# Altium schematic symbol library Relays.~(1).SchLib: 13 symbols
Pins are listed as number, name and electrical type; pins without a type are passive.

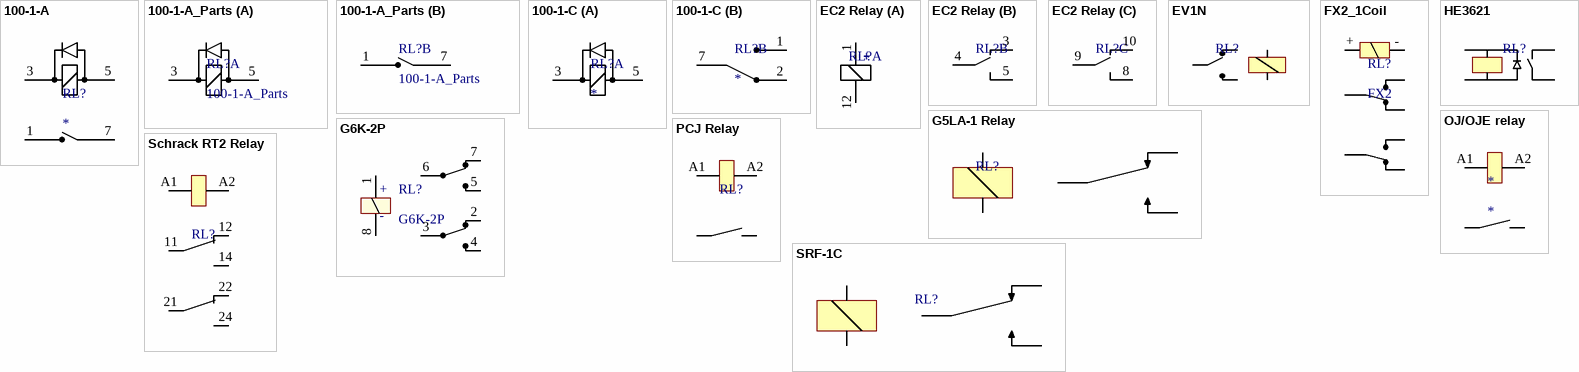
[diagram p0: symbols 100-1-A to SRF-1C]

## 100-1-A
designator RL?
footprint 100-1-A (Pickering Relay reed relay)
pins: 1 NO, 3 Coil+, 5 Coil-, 7 C

## 100-1-A_Parts
designator RL?
footprint 100-1-A (Pickering Relay reed relay)
part A pins: 3 Coil+, 5 Coil-
part B pins: 1 NO, 7 C

## 100-1-C
designator RL?
footprint 100-1-C (Pickering Relay reed relay)
part A pins: 3 Coil+, 5 Coil-
part B pins: 1 NO, 2 NC, 7 C

## EC2 Relay
designator RL?  (value not drawn)
footprint EC2 (EC2 series relay)
part A pins: 1 +, 12 -
part B pins: 3 NC, 4 C, 5 NO
part C pins: 8 NO, 9 C, 10 NC

## EV1N
designator RL?  (value not drawn)
footprint EV1N (Sub min relay)
pins: 1 NO, 2 Coil1, 3 Common, 5 Coil2, 6 NC

## FX2_1Coil
designator RL?, comment FX2
footprint FX2 relay 1 coil (FX2 relay with 1 coil); pin to pad +>1 ->10 C1>4 C2>7 NC1>3 NC2>8 NO1>5 NO2>6
pins: + COIL+, - COIL-, C1, C2, NC1, NC2, NO1, NO2

## G5LA-1 Relay
designator RL?  (value not drawn)
footprint G5LA-1 (10A CO relay)
pins: 1 Common, 2 Coil1, 3 NO, 4 NC, 5 Coil2

## G6K-2P
designator RL?
footprint G6K-2P (G6K-2P relay)
pins: 1 +, 2 NC2, 3 C2, 4 NO2, 5 NO1, 6 C1, 7 NC1, 8 -

## HE3621
designator RL?  (value not drawn)
footprint HE3621 (Hamlin Reed Relay)
pins: 1 NO, 2 +, 3 -, 4 C

## OJ/OJE relay
designator *
footprint Tyco OJ Relay (Tyco OJ/OJE relay High isolation contact/coil); pin to pad A1>1 A2>4 C>2 NO>3
pins: A1, A2, C, NO

## PCJ Relay
designator RL?  (value not drawn)
footprint PCJ Relay (TE PCJ PCB relay 3/5A contact 200mW Coil); pin to pad A1>1 A2>4 C>2 NO>3
pins: A1, A2, C, NO

## Schrack RT2 Relay
designator RL?  (value not drawn)
footprint Schrack RT2 rly (Schrack RT2 rly, 2 contacts 8A); pin to pad 11>3 12>2 14>4 21>6 22>7 24>5 A1>1 A2>8
pins: 11, 12, 14, 21, 22, 24, A1, A2

## SRF-1C
designator RL?  (value not drawn)
footprint SRF-1C Relay (IMO SRF-1C relay 1A contact 200mW coil)
pins: 1 NC, 2 Coil1, 3 Common, 4 Coil2, 5 NO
